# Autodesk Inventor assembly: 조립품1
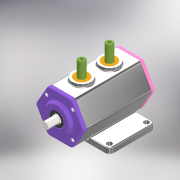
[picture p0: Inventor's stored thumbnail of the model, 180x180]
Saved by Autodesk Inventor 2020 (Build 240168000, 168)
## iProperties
Created: 2021-06
Part Number: 조립품1
Document SubType Name: Assembly
Designer: 605-5
Author: 605-5
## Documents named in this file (11)
- C:\Users\605-5\Desktop\조립품1.iam
- C:\Users\605-5\Desktop\본체.ipt
- C:\Users\605-5\Desktop\710606V1006\편심축.ipt
- C:\Users\605-5\Desktop\710606V1006\베어링 6302.ipt
- C:\Users\605-5\Desktop\710606V1006\뒷커버.ipt
- C:\Users\605-5\Desktop\710606V1006\앞커버.ipt
- C:\Users\605-5\Desktop\710606V1006\베어링 6203.ipt
- C:\Users\605-5\Desktop\710606V1006\부시.ipt
- C:\Users\605-5\Desktop\710606V1006\슬라이더.ipt
- C:\Users\605-5\Desktop\710606V1006\오일실.ipt
- C:\Users\605-5\Desktop\710606V1006\볼트 M4.ipt
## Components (10 placed, 3 different names)
1. 7-베어링 6203:1
2. 8-오일실:1
3. 9-M4-소켓머리:1
4. 9-M4-소켓머리:3
5. 9-M4-소켓머리:4
6. 9-M4-소켓머리:5
7. 9-M4-소켓머리:2
8. 9-M4-소켓머리:6
9. 9-M4-소켓머리:7
10. 9-M4-소켓머리:8
